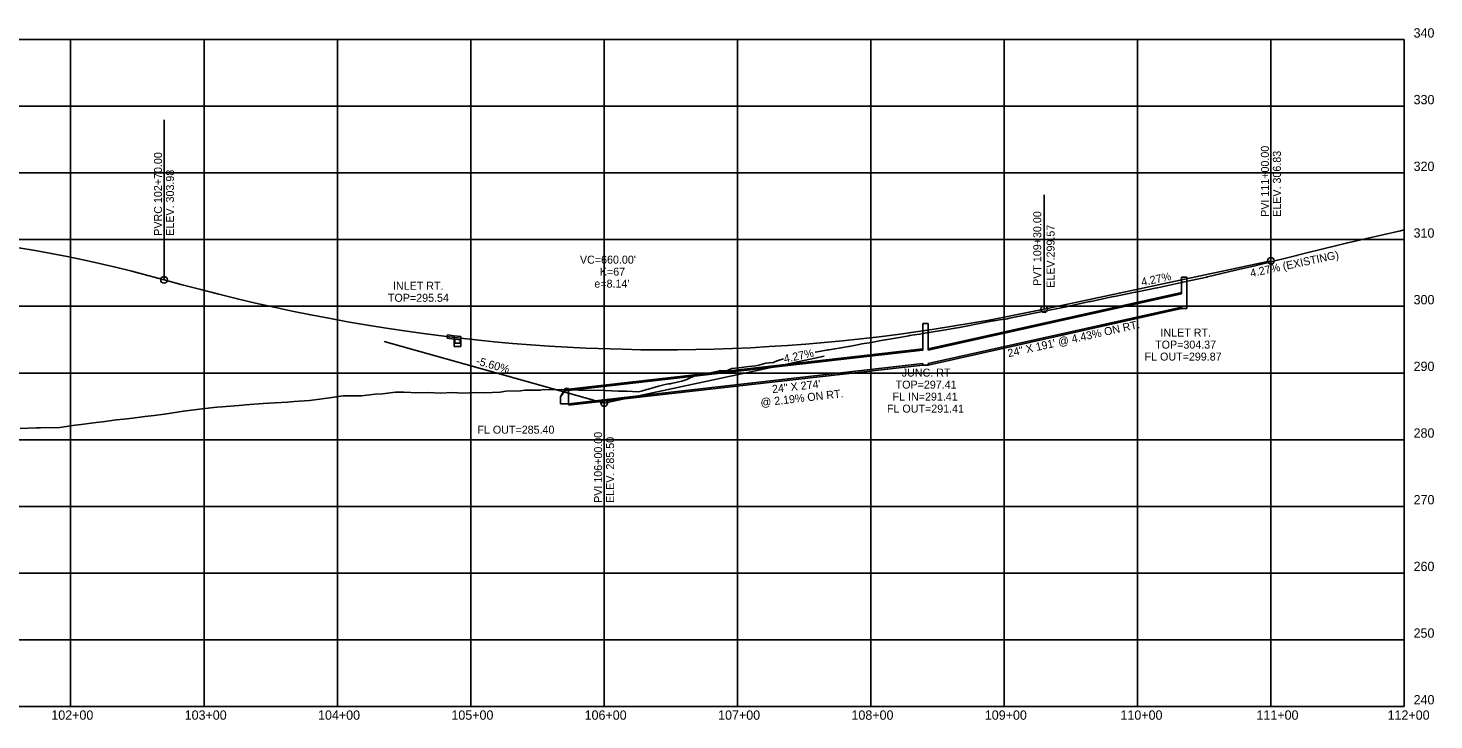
# Model space of a CAD drawing. Extents: x 1709196 to 1718257, y 543790 to 550544.
# Drawn here: x 1713258 to 1714312, y 547357 to 547876 of the extents above; entities that cross this region are included whole.
import ezdxf

# ---------------------------------------------------------------- set-up
doc = ezdxf.new("R2010")
doc.units = 0
for name, color, linetype in [('R_Axis', 7, 'Continuous'), ('R_Axis Annot', 7, 'Continuous'), ('R_Exist Surface', 7, 'Continuous'), ('R_Grid', 7, 'Continuous'), ('R_Horz Alg Annot', 7, 'Continuous'), ('R_Vert Alg', 7, 'Continuous'), ('R_Vert Alg Annot', 7, 'Continuous'), ('R_Water', 7, 'Continuous')]:
    doc.layers.add(name, color=color, linetype=linetype)

msp = doc.modelspace()

# ---------------------------------------------------------------- linework, layer by layer
at = {"layer": 'R_Axis'}
for p, q in [((1714289.7, 547367.3), (1714289.7, 547867.3)), ((1712489.7, 547367.3), (1714289.7, 547367.3))]:
    msp.add_line(p, q, dxfattribs=at)
at = {"layer": 'R_Exist Surface'}
for points in [[(1713847.9, 547633), (1713850.9, 547633.5), (1713857.7, 547634.7), (1713858.4, 547634.8), (1713862.6, 547635.5), (1713866, 547636), (1713872.8, 547637.2), (1713873.5, 547637.3), (1713881, 547638.7), (1713882.9, 547639.1), (1713888.5, 547640), (1713892.8, 547640.8), (1713896, 547641.4), (1713900.4, 547642.2), (1713903.6, 547642.7), (1713911.1, 547643.9), (1713912.8, 547644.2), (1713918.1, 547645.2), (1713918.6, 547645.3), (1713926.1, 547646.5), (1713932.8, 547647.6), (1713933.6, 547647.7), (1713936.3, 547648.2), (1713941.2, 547649), (1713948.7, 547650.2), (1713952.8, 547650.9), (1713954.5, 547651.2), (1713956.2, 547651.5), (1713963.7, 547652.9), (1713968.5, 547653.8), (1713971.2, 547654.4), (1713978.8, 547655.8), (1713981.1, 547656.3), (1713982, 547656.4), (1713982.1, 547656.4), (1713986.3, 547657.1), (1713990.2, 547657.6), (1713990.6, 547657.7), (1713992.1, 547658), (1713993.8, 547658.3), (1714001.3, 547659.9), (1714013.4, 547662.3), (1714014.6, 547662.6), (1714036.3, 547667), (1714036.9, 547667.1), (1714053.9, 547670.8), (1714054.6, 547670.9), (1714071.7, 547674.6), (1714072.3, 547674.7), (1714087.9, 547677.9), (1714088.4, 547678), (1714104.1, 547681.1), (1714104.6, 547681.2), (1714122.7, 547685.1), (1714123.1, 547685.2), (1714123.6, 547685.3), (1714141.7, 547689.2), (1714142.1, 547689.3), (1714163.2, 547694.3), (1714176.7, 547697.5), (1714184.6, 547699.3), (1714184.7, 547699.4), (1714209, 547705.4), (1714209.3, 547705.5), (1714209.6, 547705.6), (1714233.9, 547711.7), (1714234.1, 547711.7), (1714247.1, 547714.8), (1714247.3, 547714.8), (1714260.4, 547717.8), (1714260.5, 547717.9), (1714273.6, 547720.9), (1714273.7, 547721), (1714286.9, 547724), (1714286.9, 547724), (1714289.6, 547724.7)], [(1713251.9, 547575.8), (1713264.2, 547576.2), (1713267.2, 547576.2), (1713281.6, 547576.5), (1713293.2, 547578.2), (1713297.7, 547578.7), (1713308.8, 547580.3), (1713313.7, 547580.7), (1713324.2, 547582.3), (1713329.6, 547582.8), (1713336.3, 547583.4), (1713345.4, 547584.7), (1713352.3, 547585.5), (1713360.1, 547586.4), (1713369.6, 547588), (1713374.2, 547588.7), (1713384.4, 547589.9), (1713388.2, 547590.4), (1713399.2, 547591.7), (1713403.3, 547592), (1713418.9, 547593.3), (1713420.9, 547593.4), (1713434, 547594.5), (1713438.4, 547594.7), (1713452.2, 547595.4), (1713457.3, 547596), (1713468.8, 547596.7), (1713476.5, 547597.6), (1713485.5, 547598.9), (1713494, 547600.1), (1713507.7, 547600.1), (1713518, 547601.5), (1713523.6, 547601.6), (1713533.4, 547602.9), (1713539.5, 547603), (1713550.2, 547602.5), (1713557.7, 547602.7), (1713567, 547602.3), (1713575.8, 547602.6), (1713583.7, 547602.3), (1713593.8, 547602.7), (1713600.3, 547602.5), (1713611.7, 547602.9), (1713616.1, 547603.6), (1713626.9, 547603.9), (1713630.2, 547604.4), (1713642.1, 547604.5), (1713644.2, 547604.9), (1713657.3, 547604.8), (1713658.1, 547604.9), (1713664.7, 547604.7), (1713670.7, 547604.5), (1713672.7, 547604.3), (1713685.5, 547604.4), (1713690.6, 547604.2), (1713700.6, 547603.7), (1713706.4, 547603.7), (1713715.4, 547603.1), (1713715.6, 547603.2), (1713718.4, 547604), (1713721.7, 547604.9), (1713723.1, 547605.3), (1713727.9, 547606.7), (1713730.6, 547607.4), (1713735.4, 547608.6), (1713738.1, 547609.1), (1713739.2, 547609.3), (1713740.1, 547609.4), (1713745.7, 547610.6), (1713748.1, 547611.1), (1713751.7, 547612.5), (1713753.2, 547613.2), (1713756.5, 547614.6), (1713757.6, 547615.3), (1713760.7, 547615.9), (1713768.2, 547617.3), (1713773.9, 547618.4), (1713775.7, 547618.8), (1713776.7, 547619.1), (1713778.3, 547618.9), (1713781.6, 547619), (1713783.3, 547619.7), (1713785.6, 547620.6), (1713790.8, 547621.2), (1713798.3, 547622.1), (1713803.4, 547622.7), (1713803.6, 547622.7), (1713805.8, 547623.3), (1713810.9, 547624.7), (1713813.3, 547624.9), (1713816.8, 547625.2), (1713817.5, 547625.8), (1713820.9, 547626.9), (1713824.1, 547627.9)]]:
    msp.add_lwpolyline(points, dxfattribs=at)
at = {"layer": 'R_Grid'}
for p, q in [((1712489.7, 547867.3), (1714289.7, 547867.3)), ((1712489.7, 547867.3), (1714289.7, 547867.3)), ((1713289.7, 547367.3), (1713289.7, 547867.3)), ((1713389.7, 547367.3), (1713389.7, 547867.3)), ((1713489.7, 547367.3), (1713489.7, 547867.3)), ((1713589.7, 547367.3), (1713589.7, 547867.3)), ((1713689.7, 547367.3), (1713689.7, 547867.3)), ((1713789.7, 547367.3), (1713789.7, 547867.3)), ((1713889.7, 547367.3), (1713889.7, 547867.3)), ((1713989.7, 547367.3), (1713989.7, 547867.3)), ((1714089.7, 547367.3), (1714089.7, 547867.3)), ((1714189.7, 547367.3), (1714189.7, 547867.3)), ((1712489.7, 547817.3), (1714289.7, 547817.3)), ((1712489.7, 547767.3), (1714289.7, 547767.3)), ((1712489.7, 547717.3), (1714289.7, 547717.3)), ((1712489.7, 547667.3), (1714289.7, 547667.3)), ((1712489.7, 547617.3), (1714289.7, 547617.3)), ((1712489.7, 547567.3), (1714289.7, 547567.3)), ((1712489.7, 547517.3), (1714289.7, 547517.3)), ((1712489.7, 547467.3), (1714289.7, 547467.3)), ((1712489.7, 547417.3), (1714289.7, 547417.3))]:
    msp.add_line(p, q, dxfattribs=at)
at = {"layer": 'R_Vert Alg'}
for p, q in [((1714019.7, 547665.2), (1714189.7, 547701.4)), ((1713524.7, 547641), (1713689.7, 547594.8)), ((1713689.7, 547594.8), (1713854.7, 547630))]:
    msp.add_line(p, q, dxfattribs=at)
for points in [[(1713250.9, 547711.2), (1713263, 547709.2), (1713275.1, 547707), (1713287.2, 547704.6), (1713299.2, 547702.1), (1713311.3, 547699.4), (1713323.4, 547696.6), (1713335.5, 547693.6), (1713347.6, 547690.5), (1713359.7, 547687.2)], [(1713359.7, 547687.2), (1713373.4, 547683.4), (1713387.2, 547679.8), (1713400.9, 547676.3), (1713414.7, 547672.9), (1713428.4, 547669.7), (1713442.2, 547666.6), (1713455.9, 547663.7), (1713469.7, 547660.9), (1713483.4, 547658.3), (1713497.2, 547655.7), (1713510.9, 547653.4), (1713524.7, 547651.2), (1713538.4, 547649.1), (1713552.2, 547647.1), (1713565.9, 547645.3), (1713579.7, 547643.7), (1713593.4, 547642.2), (1713607.2, 547640.8), (1713620.9, 547639.5), (1713634.7, 547638.4), (1713648.4, 547637.5), (1713662.2, 547636.7), (1713675.9, 547636), (1713703.4, 547635.1), (1713717.2, 547634.8), (1713730.9, 547634.7), (1713744.7, 547634.8), (1713758.4, 547635), (1713772.2, 547635.3), (1713785.9, 547635.7), (1713799.7, 547636.3), (1713813.4, 547637.1), (1713827.2, 547638), (1713840.9, 547639), (1713854.7, 547640.2), (1713868.4, 547641.5), (1713882.2, 547642.9), (1713895.9, 547644.5), (1713909.7, 547646.2), (1713923.4, 547648.1), (1713937.2, 547650.1), (1713950.9, 547652.3), (1713964.7, 547654.6), (1713978.4, 547657), (1713992.2, 547659.6), (1714005.9, 547662.3), (1714019.7, 547665.2)]]:
    msp.add_lwpolyline(points, dxfattribs=at)
at = {"layer": 'R_Vert Alg Annot'}
for p, q in [((1714189.7, 547731.4), (1714189.7, 547815.4)), ((1713359.7, 547717.2), (1713359.7, 547807.2)), ((1714019.7, 547695.2), (1714019.7, 547750.9)), ((1714189.7, 547701.4), (1714189.7, 547731.4)), ((1713359.7, 547687.2), (1713359.7, 547717.2)), ((1714019.7, 547665.2), (1714019.7, 547695.2)), ((1713660.5, 547605.6), (1713656.9, 547599.5)), ((1713660.5, 547604.3), (1713656.9, 547599.5)), ((1713663, 547605.6), (1713660.5, 547605.6)), ((1713660.5, 547605.6), (1713660.5, 547604.3)), ((1713663, 547604.3), (1713660.5, 547604.3)), ((1713663, 547594.3), (1713663, 547605.6)), ((1713656.9, 547594.3), (1713656.9, 547599.5)), ((1713663, 547594.3), (1713656.9, 547594.3)), ((1713689.7, 547594.8), (1713689.7, 547564.8)), ((1713689.7, 547564.8), (1713689.7, 547480.8))]:
    msp.add_line(p, q, dxfattribs=at)
for centre in [(1714189.7, 547701.4), (1713359.7, 547687.2), (1714019.7, 547665.2), (1713689.7, 547594.8)]:
    msp.add_circle(centre, 2.5, dxfattribs=at)
at = {"layer": 'R_Water'}
for p, q in [((1713572.2, 547645.8), (1713572.1, 547643.3)), ((1713582.2, 547644.7), (1713577.2, 547645.2)), ((1713577.2, 547644.8), (1713577.2, 547637.2)), ((1713582.2, 547644.7), (1713582.2, 547637.2)), ((1713582.2, 547637.2), (1713577.2, 547637.2)), ((1713577.7, 547642.6), (1713577.7, 547639.7)), ((1713581.7, 547642.2), (1713577.7, 547642.6)), ((1713581.7, 547639.7), (1713577.7, 547639.7)), ((1713581.7, 547642.2), (1713581.7, 547639.7))]:
    msp.add_line(p, q, dxfattribs=at)
for points in [[(1714126.7, 547689.1), (1714122.7, 547689.1)], [(1714122.7, 547689.1), (1714122.7, 547676.6)], [(1714126.7, 547666.6), (1714126.7, 547689.1)], [(1714122.7, 547677.6), (1713932.7, 547635.4)], [(1714122.7, 547676.6), (1713932.7, 547634.4)], [(1714122.7, 547666.6), (1713932.7, 547624.4)], [(1714122.7, 547665.6), (1713932.7, 547623.3)], [(1714122.7, 547665.6), (1714122.7, 547666.6)], [(1714126.7, 547665.6), (1714122.7, 547665.6)], [(1714126.7, 547666.6), (1714126.7, 547665.6)], [(1713932.7, 547654.4), (1713928.7, 547654.4)], [(1713928.7, 547654.4), (1713928.7, 547634.4)], [(1713932.7, 547634.4), (1713932.7, 547654.4)], [(1713572.1, 547643.3), (1713577.2, 547642.7), (1713577.2, 547645.2), (1713572.2, 547645.8)], [(1713928.7, 547635.4), (1713663, 547605.3)], [(1713928.7, 547634.4), (1713663, 547604.3)], [(1713928.7, 547624.4), (1713663, 547594.3)], [(1713928.7, 547623.3), (1713663, 547593.3)], [(1713928.7, 547623.3), (1713928.7, 547624.4)], [(1713932.7, 547623.3), (1713928.7, 547623.3)], [(1713932.7, 547624.4), (1713932.7, 547623.3)]]:
    msp.add_lwpolyline(points, dxfattribs=at)

# ---------------------------------------------------------------- texts
at = {"layer": 'R_Axis Annot'}
for s, p in [('340', (1714296.7, 547868.8)), ('340', (1714296.7, 547868.8)), ('330', (1714296.7, 547818.8)), ('320', (1714296.7, 547768.8)), ('310', (1714296.7, 547718.8)), ('300', (1714296.7, 547668.8)), ('290', (1714296.7, 547618.8)), ('280', (1714296.7, 547568.8)), ('270', (1714296.7, 547518.8)), ('260', (1714296.7, 547468.8)), ('250', (1714296.7, 547418.8)), ('240', (1714296.7, 547368.8)), ('102+00', (1713275.2, 547357.3)), ('103+00', (1713375.2, 547357.3)), ('104+00', (1713475.2, 547357.3)), ('105+00', (1713575.2, 547357.3)), ('106+00', (1713675.1, 547357.3)), ('107+00', (1713775.2, 547357.3)), ('108+00', (1713875.2, 547357.3)), ('109+00', (1713975.2, 547357.3)), ('110+00', (1714076.9, 547357.3)), ('111+00', (1714178.9, 547357.3)), ('112+00', (1714277.2, 547357.3))]:
    msp.add_text(s, height=7, dxfattribs=at).set_placement(p)
at = {"layer": 'R_Horz Alg Annot'}
for s, rotation, p in [('4.27% (EXISTING)', 12.0629, (1714174.8, 547689.1)), ('4.27%', 12.0403, (1713825.1, 547624.9)), ('-5.60%', 344.3578, (1713593.3, 547623.8))]:
    msp.add_text(s, height=6, rotation=rotation, dxfattribs=at).set_placement(p)
at = {"layer": 'R_Vert Alg Annot'}
for s, rotation, p in [('PVRC 102+70.00', 90, (1713358.2, 547720.2)), ('PVI 111+00.00', 90, (1714188.2, 547734.4)), ('ELEV. 306.83', 90, (1714197.2, 547734.4)), ('ELEV. 303.98', 90, (1713367.2, 547720.2)), ('PVT 109+30.00', 90, (1714017.5, 547682.6)), ('ELEV.299.57', 90, (1714027.5, 547681.2)), ('4.27%', 12.0403, (1714093.1, 547682.4)), ('24" X 191\' @ 4.43% ON RT.', 12.535, (1713993, 547629.1)), ('24" X 274\' ', 6.4525, (1713816, 547602.2)), ('@ 2.19% ON RT.', 6.4525, (1713807.3, 547592.1)), ('PVI 106+00.00', 90, (1713688.2, 547519.9)), ('ELEV. 285.50', 90, (1713697.2, 547519.9))]:
    msp.add_text(s, height=6, rotation=rotation, dxfattribs=at).set_placement(p)
for s, p in [("VC=660.00'", (1713671.6, 547699.3)), ('K=67', (1713686.5, 547690.3)), ('INLET RT.', (1713531.4, 547679.7)), ("e=8.14'", (1713682.4, 547681.3)), ('TOP=295.54', (1713527.6, 547670.7)), ('INLET RT.', (1714106.9, 547644.6)), ('FL OUT=299.87', (1714095, 547626.6)), ('TOP=304.37', (1714102.9, 547635.6)), ('TOP=297.41', (1713908.3, 547605.6)), ('JUNC. RT', (1713912.9, 547614.6)), (' FL IN=291.41', (1713903.8, 547596.6)), ('FL OUT=291.41', (1713901.8, 547587.6)), ('FL OUT=285.40', (1713594.7, 547571.8))]:
    msp.add_text(s, height=6, dxfattribs=at).set_placement(p)

doc.saveas('drawing.dxf')
